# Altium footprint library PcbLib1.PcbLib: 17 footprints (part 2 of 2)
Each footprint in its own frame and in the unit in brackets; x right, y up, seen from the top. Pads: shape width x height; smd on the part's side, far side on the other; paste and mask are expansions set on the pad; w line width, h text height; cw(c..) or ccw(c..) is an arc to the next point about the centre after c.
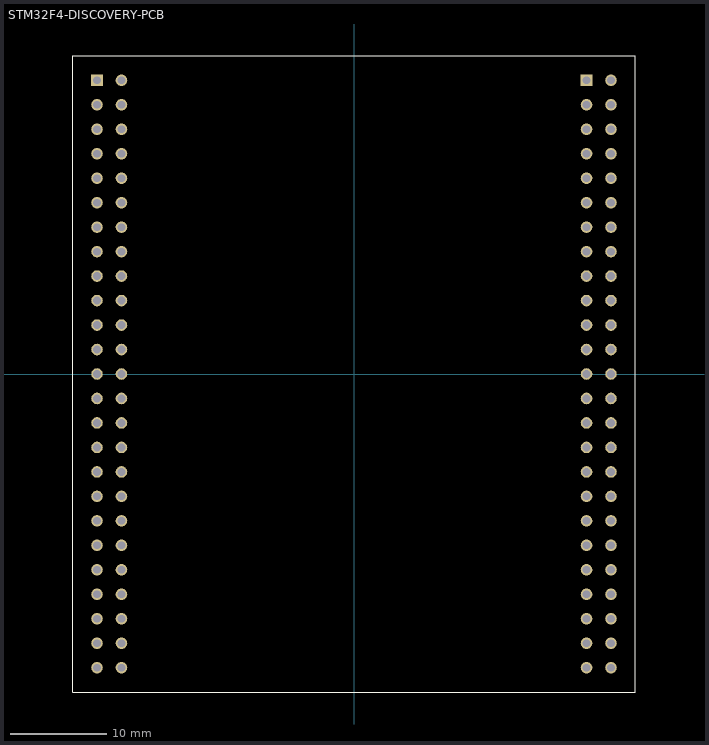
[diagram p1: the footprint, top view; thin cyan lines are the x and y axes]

## STM32F4-DISCOVERY-PCB [mil]
pads (100):
  rect 47.25x47.25 hole 31.5: P1_1(-1050,1200) P2_1(950,1200)
  round 47.25 hole 31.5: P1_2(-950,1200) P1_3(-1050,1100) P1_4(-950,1100) P1_5(-1050,1000) P1_6(-950,1000) P1_7(-1050,900) P1_8(-950,900) P1_9(-1050,800) P1_10(-950,800) P1_11(-1050,700) P1_12(-950,700) P1_13(-1050,600) P1_14(-950,600) P1_15(-1050,500) P1_16(-950,500) P1_17(-1050,400) P1_18(-950,400) P1_19(-1050,300) P1_20(-950,300) P1_21(-1050,200) P1_22(-950,200) P1_23(-1050,100) P1_24(-950,100) P1_25(-1050,0) P1_26(-950,0) P1_27(-1050,-100) P1_28(-950,-100) P1_29(-1050,-200) P1_30(-950,-200) P1_31(-1050,-300) P1_32(-950,-300) P1_33(-1050,-400) P1_34(-950,-400) P1_35(-1050,-500) P1_36(-950,-500) P1_37(-1050,-600) P1_38(-950,-600) P1_39(-1050,-700) P1_40(-950,-700) P1_41(-1050,-800) P1_42(-950,-800) P1_43(-1050,-900) P1_44(-950,-900) P1_45(-1050,-1000) P1_46(-950,-1000) P1_47(-1050,-1100) P1_48(-950,-1100) P1_49(-1050,-1200) P1_50(-950,-1200) P2_2(1050,1200) P2_3(950,1100) P2_4(1050,1100) P2_5(950,1000) P2_6(1050,1000) P2_7(950,900) P2_8(1050,900) P2_9(950,800) P2_10(1050,800) P2_11(950,700) P2_12(1050,700) P2_13(950,600) P2_14(1050,600) P2_15(950,500) P2_16(1050,500) P2_17(950,400) P2_18(1050,400) P2_19(950,300) P2_20(1050,300) P2_21(950,200) P2_22(1050,200) P2_23(950,100) P2_24(1050,100) P2_25(950,0) P2_26(1050,0) P2_27(950,-100) P2_28(1050,-100) P2_29(950,-200) P2_30(1050,-200) P2_31(950,-300) P2_32(1050,-300) P2_33(950,-400) P2_34(1050,-400) P2_35(950,-500) P2_36(1050,-500) P2_37(950,-600) P2_38(1050,-600) P2_39(950,-700) P2_40(1050,-700) P2_41(950,-800) P2_42(1050,-800) P2_43(950,-900) P2_44(1050,-900) P2_45(950,-1000) P2_46(1050,-1000) P2_47(950,-1100) P2_48(1050,-1100) P2_49(950,-1200) P2_50(1050,-1200)
Top Overlay:
  lines w5: -1150,-1300 -1150,1300 1150,1300 1150,-1300 -1150,-1300
3D body "stm30f4.SLDPRT": height 854.33, standoff -51.18, extent -1290,-1455 1288.74,2583.04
